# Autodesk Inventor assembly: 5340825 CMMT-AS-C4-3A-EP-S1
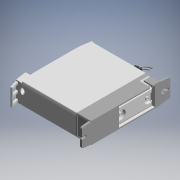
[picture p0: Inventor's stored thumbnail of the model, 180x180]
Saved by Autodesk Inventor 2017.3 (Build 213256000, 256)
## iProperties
Category: PARTsolutions
Company: FESTO
Part Number: 5340825 CMMT-AS-C4-3A-EP-S1
Catalog Web Link: www.cadenas.de
Description: CMMT-servo drive
Vendor: FESTO
Document SubType Name: Assembly
Designer: partserver
Manufacturer: FESTO
Mass: 1400 g
Surface Area: 1425.08 cm^2
Volume: 1409.13 cm^3
Density: 0.993519 g/cm^3
Title: 5340825 CMMT-AS-C4-3A-EP-S1
Author: Cadenas PARTsolutions
Comments: servo drive
PSOL_IDENT_0: {ATYP=ASSISTANT},{DATA=script=$CADENAS_DATA/23d-libs/festo/webfesto.vbb&M_FAMILY=CMMT&M_GROUP=01&M_P
PSOL_IDENT_1: ARTNO=5340825&IDCODE1=CMMT-AS-C4-3A-EP-S1&IDCODE2=&customer_number_cns=&MATES=1&LOD=HI&LOCKERP=0&SIN
PSOL_IDENT_2: GLEPART=1}
NB: 5340825 CMMT-AS-C4-3A-EP-S1
NN: CMMT
NT: servo drive
NBSYN: $TNR. $TYP.
LINA: 5340825 CMMT-AS-C4-3A-EP-S1
CATALOG: Festo
TNR: 5340825
TYP: CMMT-AS-C4-3A-EP-S1
B1: 0
B2: 0
B3: 0
D1: 0
D2: 0
D3: 0
H1: 0
H2: 0
L1: 0
L2: 0
L3: 0
L4: 0
L5: 0
L6: 0
L7: 0
CNSMASSEXACT: 1.4
SUPPLIER: FESTO
ARTICLENO: 5340825 CMMT-AS-C4-3A-EP-S1
BOMINFO: 5340825 CMMT-AS-C4-3A-EP-S1
CREATOR: CADENAS GmbH
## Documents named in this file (6)
- e:\temp\worker_11\temp\exporttempdir_6360_236_XeDxo\format_0\5340825 CMMT-AS-C4-3A-EP-S1.iam
- e:\temp\worker_11\temp\exporttempdir_6360_236_XeDxo\format_0\5340825 CMMT-AS-C4-3A-EP-S1---(h).ipt
- e:\temp\worker_11\temp\exporttempdir_6360_236_XeDxo\format_0\5395254 CAFC-C6-C.ipt
- e:\temp\worker_11\temp\exporttempdir_6360_236_XeDxo\format_0\4978445 CMMT-AS-3A---(clamp).ipt
- e:\temp\worker_11\temp\exporttempdir_6360_236_XeDxo\format_0\ISO 14580 M4x16.ipt
- e:\temp\worker_11\temp\exporttempdir_6360_236_XeDxo\format_0\4021832 2GD-1RR7_62-CLP-CBL.ipt
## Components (6 placed, 5 different names)
1. 5340825 CMMT-AS-C4-3A-EP-S1---(h):1 — COVER_XY@1 <-> ANBAU_XY@2, COVER_Z@1 <-> ANBAU_Z@2, COVER_YZ@1 <-> ANBAU_YZ@2, CLAMP_XY@1 <-> ANBAU_XY@3, CLAMP_Z@1 <-> ANBAU_Z@3, CLAMP_YZ@1 <-> ANBAU_YZ@3, PLUG_XY@1 <-> ANBAU_XY@6, PLUG_Z@1 <-> ANBAU_Z@6, PLUG_YZ@1 <-> ANBAU_YZ@6
2. 5395254 CAFC-C6-C:1 — COVER_XY@1 <-> ANBAU_XY@2, COVER_Z@1 <-> ANBAU_Z@2, COVER_YZ@1 <-> ANBAU_YZ@2
3. 4978445 CMMT-AS-3A---(clamp):1 — CLAMP_XY@1 <-> ANBAU_XY@3, CLAMP_Z@1 <-> ANBAU_Z@3, CLAMP_YZ@1 <-> ANBAU_YZ@3, SCREW_1_XY@3 <-> IP1_XY@4, SCREW_1_Z@3 <-> IP1_Z@4, SCREW_1_YZ@3 <-> IP1_YZ@4, SCREW_2_XY@3 <-> IP1_XY@5, SCREW_2_Z@3 <-> IP1_Z@5, SCREW_2_YZ@3 <-> IP1_YZ@5
4. ISO 14580 M4x16:1 — SCREW_1_XY@3 <-> IP1_XY@4, SCREW_1_Z@3 <-> IP1_Z@4, SCREW_1_YZ@3 <-> IP1_YZ@4
5. ISO 14580 M4x16:2 — SCREW_2_XY@3 <-> IP1_XY@5, SCREW_2_Z@3 <-> IP1_Z@5, SCREW_2_YZ@3 <-> IP1_YZ@5
6. 4021832 2GD-1RR7_62-CLP-CBL:1 — PLUG_XY@1 <-> ANBAU_XY@6, PLUG_Z@1 <-> ANBAU_Z@6, PLUG_YZ@1 <-> ANBAU_YZ@6
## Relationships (15: Mate 10, Angle 5)
- COVER_XY@1 <-> ANBAU_XY@2 [Mate]: 5340825 CMMT-AS-C4-3A-EP-S1---(h):1 ↔ 5395254 CAFC-C6-C:1
- COVER_Z@1 <-> ANBAU_Z@2 [Mate]: 5340825 CMMT-AS-C4-3A-EP-S1---(h):1 ↔ 5395254 CAFC-C6-C:1
- COVER_YZ@1 <-> ANBAU_YZ@2 [Angle]: 5340825 CMMT-AS-C4-3A-EP-S1---(h):1 ↔ 5395254 CAFC-C6-C:1
- CLAMP_XY@1 <-> ANBAU_XY@3 [Mate]: 5340825 CMMT-AS-C4-3A-EP-S1---(h):1 ↔ 4978445 CMMT-AS-3A---(clamp):1
- CLAMP_Z@1 <-> ANBAU_Z@3 [Mate]: 5340825 CMMT-AS-C4-3A-EP-S1---(h):1 ↔ 4978445 CMMT-AS-3A---(clamp):1
- CLAMP_YZ@1 <-> ANBAU_YZ@3 [Angle]: 5340825 CMMT-AS-C4-3A-EP-S1---(h):1 ↔ 4978445 CMMT-AS-3A---(clamp):1
- SCREW_1_XY@3 <-> IP1_XY@4 [Mate]: 4978445 CMMT-AS-3A---(clamp):1 ↔ ISO 14580 M4x16:1
- SCREW_1_Z@3 <-> IP1_Z@4 [Mate]: 4978445 CMMT-AS-3A---(clamp):1 ↔ ISO 14580 M4x16:1
- SCREW_1_YZ@3 <-> IP1_YZ@4 [Angle]: 4978445 CMMT-AS-3A---(clamp):1 ↔ ISO 14580 M4x16:1
- SCREW_2_XY@3 <-> IP1_XY@5 [Mate]: 4978445 CMMT-AS-3A---(clamp):1 ↔ ISO 14580 M4x16:2
- SCREW_2_Z@3 <-> IP1_Z@5 [Mate]: 4978445 CMMT-AS-3A---(clamp):1 ↔ ISO 14580 M4x16:2
- SCREW_2_YZ@3 <-> IP1_YZ@5 [Angle]: 4978445 CMMT-AS-3A---(clamp):1 ↔ ISO 14580 M4x16:2
- PLUG_XY@1 <-> ANBAU_XY@6 [Mate]: 5340825 CMMT-AS-C4-3A-EP-S1---(h):1 ↔ 4021832 2GD-1RR7_62-CLP-CBL:1
- PLUG_Z@1 <-> ANBAU_Z@6 [Mate]: 5340825 CMMT-AS-C4-3A-EP-S1---(h):1 ↔ 4021832 2GD-1RR7_62-CLP-CBL:1
- PLUG_YZ@1 <-> ANBAU_YZ@6 [Angle]: 5340825 CMMT-AS-C4-3A-EP-S1---(h):1 ↔ 4021832 2GD-1RR7_62-CLP-CBL:1
